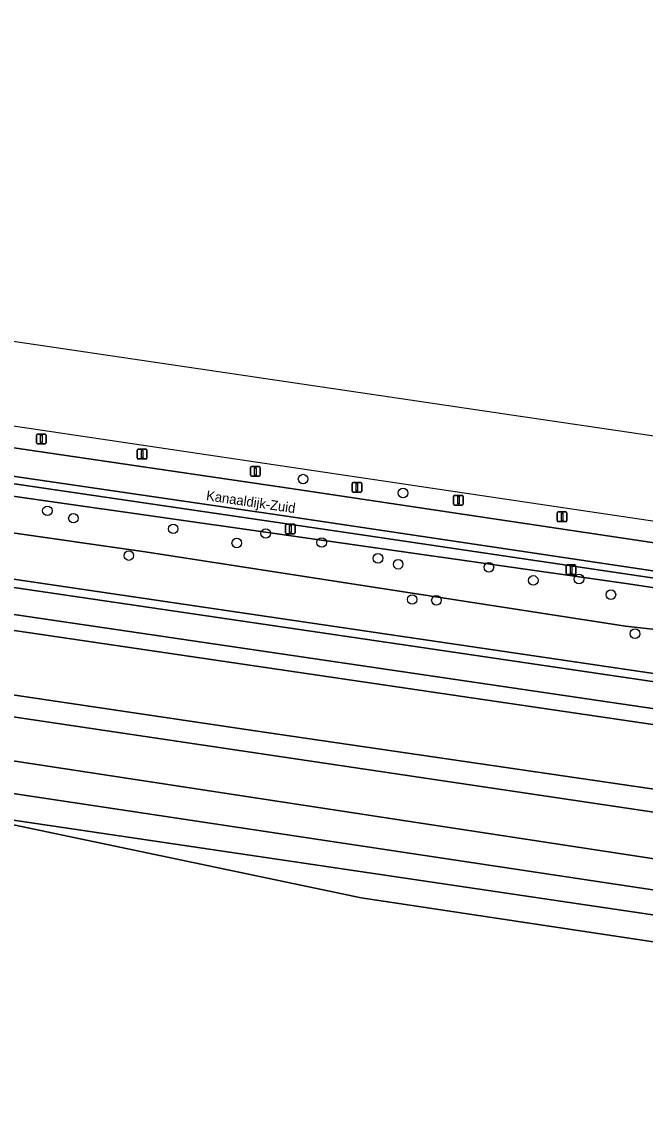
# Model space of a CAD drawing. Extents: x 163043 to 165076, y 382019 to 382874.
# Drawn here: x 163631.7 to 163695.7, y 382706.9 to 382817.6 of the extents above; entities that cross this region are included whole.
import ezdxf

# ---------------------------------------------------------------- set-up
doc = ezdxf.new("R2010")
doc.units = 0
for name, color, linetype in [('IMGEO_Afsluitpaal', 7, 'Continuous'), ('IMGEO_Berm_groen', 7, 'Continuous'), ('IMGEO_Boom', 7, 'Continuous'), ('IMGEO_Erf', 7, 'Continuous'), ('IMGEO_Fietspad_gesloten', 7, 'Continuous'), ('IMGEO_Groenvoorziening', 7, 'Continuous'), ('IMGEO_Hek', 7, 'Continuous'), ('IMGEO_Lichtmast', 7, 'Continuous'), ('IMGEO_Oever', 7, 'Continuous'), ('IMGEO_Openbare_ruimte_label', 7, 'Continuous'), ('IMGEO_Rijbaan_lokaal_gesloten', 7, 'Continuous'), ('IMGEO_Rijbaan_lokaal_halfverhard', 7, 'Continuous'), ('IMGEO_Waterloop', 7, 'Continuous')]:
    doc.layers.add(name, color=color, linetype=linetype)

msp = doc.modelspace()

# ---------------------------------------------------------------- linework, layer by layer
at = {"layer": 'IMGEO_Afsluitpaal'}
for p, q in [((163633.25, 382774.48), (163633.25, 382775.28)), ((163633.25, 382775.28), (163633.25, 382774.48)), ((163633.35, 382775.38), (163634.14, 382775.38)), ((163634.14, 382775.38), (163633.35, 382775.38)), ((163634.24, 382775.28), (163634.24, 382774.48)), ((163634.24, 382774.48), (163634.24, 382775.28)), ((163634.14, 382774.38), (163633.35, 382774.38)), ((163633.35, 382774.38), (163634.14, 382774.38)), ((163643.59, 382772.93), (163643.59, 382773.73)), ((163643.59, 382773.73), (163643.59, 382772.93)), ((163643.69, 382773.83), (163644.48, 382773.83)), ((163644.48, 382773.83), (163643.69, 382773.83)), ((163644.48, 382772.83), (163643.69, 382772.83)), ((163643.69, 382772.83), (163644.48, 382772.83)), ((163644.58, 382773.73), (163644.58, 382772.93)), ((163644.58, 382772.93), (163644.58, 382773.73)), ((163655.19, 382771.16), (163655.19, 382771.96)), ((163655.19, 382771.96), (163655.19, 382771.16)), ((163655.29, 382772.06), (163656.07, 382772.06)), ((163656.07, 382772.06), (163655.29, 382772.06)), ((163656.17, 382771.96), (163656.17, 382771.16)), ((163656.17, 382771.16), (163656.17, 382771.96)), ((163656.07, 382771.06), (163655.29, 382771.06)), ((163655.29, 382771.06), (163656.07, 382771.06)), ((163665.6, 382769.53), (163665.6, 382770.33)), ((163665.6, 382770.33), (163665.6, 382769.53)), ((163665.7, 382770.43), (163666.49, 382770.43)), ((163666.49, 382770.43), (163665.7, 382770.43)), ((163666.59, 382770.33), (163666.59, 382769.53)), ((163666.59, 382769.53), (163666.59, 382770.33)), ((163666.49, 382769.43), (163665.7, 382769.43)), ((163665.7, 382769.43), (163666.49, 382769.43)), ((163676.01, 382768.2), (163676.01, 382769)), ((163676.01, 382769), (163676.01, 382768.2)), ((163676.11, 382769.1), (163676.9, 382769.1)), ((163676.9, 382769.1), (163676.11, 382769.1)), ((163677, 382769), (163677, 382768.2)), ((163677, 382768.2), (163677, 382769)), ((163676.9, 382768.1), (163676.11, 382768.1)), ((163676.11, 382768.1), (163676.9, 382768.1)), ((163686.64, 382766.51), (163686.64, 382767.31)), ((163686.64, 382767.31), (163686.64, 382766.51)), ((163686.74, 382767.41), (163687.53, 382767.41)), ((163687.53, 382767.41), (163686.74, 382767.41)), ((163687.63, 382767.31), (163687.63, 382766.51)), ((163687.63, 382766.51), (163687.63, 382767.31)), ((163687.53, 382766.41), (163686.74, 382766.41)), ((163686.74, 382766.41), (163687.53, 382766.41))]:
    msp.add_line(p, q, dxfattribs=at)
for points in [[(163633.67, 382775.26), (163633.82, 382775.26), (163633.82, 382774.51), (163633.67, 382774.51), (163633.67, 382775.26)], [(163644.01, 382773.71), (163644.16, 382773.71), (163644.16, 382772.96), (163644.01, 382772.96), (163644.01, 382773.71)], [(163655.6, 382771.93), (163655.76, 382771.93), (163655.76, 382771.18), (163655.6, 382771.18), (163655.6, 382771.93)], [(163666.02, 382770.31), (163666.17, 382770.31), (163666.17, 382769.56), (163666.02, 382769.56), (163666.02, 382770.31)], [(163676.43, 382768.98), (163676.58, 382768.98), (163676.58, 382768.23), (163676.43, 382768.23), (163676.43, 382768.98)], [(163687.06, 382767.28), (163687.21, 382767.28), (163687.21, 382766.53), (163687.06, 382766.53), (163687.06, 382767.28)]]:
    msp.add_lwpolyline(points, dxfattribs=at)
for centre, start, end in [((163633.35, 382775.28), 90, 180), ((163633.35, 382775.28), 90, 180), ((163634.14, 382775.28), 0, 90), ((163634.14, 382775.28), 360, 90), ((163633.35, 382774.48), 180, 270), ((163633.35, 382774.48), 180, 270), ((163634.14, 382774.48), 270, 0), ((163634.14, 382774.48), 270, 0), ((163643.69, 382773.73), 90, 180), ((163643.69, 382773.73), 90, 180), ((163643.69, 382772.93), 180, 270), ((163643.69, 382772.93), 180, 270), ((163644.48, 382773.73), 0, 90), ((163644.48, 382773.73), 360, 90), ((163644.48, 382772.93), 270, 0), ((163644.48, 382772.93), 270, 0), ((163655.29, 382771.96), 90, 180), ((163655.29, 382771.96), 90, 180), ((163656.07, 382771.96), 0, 90), ((163656.07, 382771.96), 360, 90), ((163655.29, 382771.16), 180, 270), ((163655.29, 382771.16), 180, 270), ((163656.07, 382771.16), 270, 0), ((163656.07, 382771.16), 270, 0), ((163665.7, 382770.33), 90, 180), ((163665.7, 382770.33), 90, 180), ((163665.7, 382769.53), 180, 270), ((163665.7, 382769.53), 180, 270), ((163666.49, 382770.33), 0, 90), ((163666.49, 382770.33), 360, 90), ((163666.49, 382769.53), 270, 0), ((163666.49, 382769.53), 270, 0), ((163676.11, 382769), 90, 180), ((163676.11, 382769), 90, 180), ((163676.9, 382769), 0, 90), ((163676.9, 382769), 360, 90), ((163676.11, 382768.2), 180, 270), ((163676.11, 382768.2), 180, 270), ((163676.9, 382768.2), 270, 0), ((163676.9, 382768.2), 270, 0), ((163686.74, 382767.31), 90, 180), ((163686.74, 382767.31), 90, 180), ((163687.53, 382767.31), 0, 90), ((163687.53, 382767.31), 360, 90), ((163686.74, 382766.51), 180, 270), ((163686.74, 382766.51), 180, 270), ((163687.53, 382766.51), 270, 0), ((163687.53, 382766.51), 270, 0)]:
    msp.add_arc(centre, 0.1, start, end, dxfattribs=at)
at = {"layer": 'IMGEO_Berm_groen'}
msp.add_lwpolyline([(163557.09, 382767.74), (163556.9, 382766.15), (163666.72, 382750), (163831.84, 382725.71), (163843.6, 382723.98), (163843.81, 382725.57)], close=True, dxfattribs=at)
at = {"layer": 'IMGEO_Boom'}
for centre in [(163660.58, 382770.77), (163670.83, 382769.34), (163634.37, 382767.52), (163637.04, 382766.76), (163647.27, 382765.67), (163656.75, 382765.2), (163653.78, 382764.22), (163662.49, 382764.27), (163642.72, 382762.93), (163668.26, 382762.65), (163670.33, 382762.04), (163679.63, 382761.73), (163684.18, 382760.39), (163688.87, 382760.53), (163671.77, 382758.43), (163674.25, 382758.35), (163692.14, 382758.93), (163694.61, 382754.93)]:
    msp.add_circle(centre, 0.489, dxfattribs=at)
at = {"layer": 'IMGEO_Erf'}
for points in [[(163755.9, 382730.2), (163716.68, 382736.05), (163656.59, 382744.84), (163592.57, 382754.34), (163555.64, 382759.8), (163555.43, 382758.28), (163551.14, 382758.95), (163550.79, 382757.63)], [(163550, 382756.08), (163551.21, 382757), (163551.71, 382756.34), (163551.82, 382757.15), (163552.77, 382757.02), (163552.78, 382757.12), (163555.08, 382756.83), (163555.19, 382757.61), (163606.71, 382750), (163755.55, 382727.85)], [(163753.68, 382717.65), (163616.32, 382737.96)], [(163517.69, 382649.12), (163518.33, 382648.93), (163518.9, 382648.81), (163519.65, 382648.65), (163520.31, 382648.5), (163520.96, 382648.34), (163520.6, 382646.87), (163561.84, 382636.86), (163562.82, 382641.11), (163587.18, 382635.48), (163586.11, 382630.84), (163589.84, 382629.98), (163598.25, 382663.73), (163605.6, 382662.09), (163616.25, 382704.79), (163625.48, 382736.46), (163666.55, 382727.85), (163754.11, 382714.7), (163754.37, 382714.66)], [(163838.28, 382702.34), (163806.26, 382707.16), (163779.91, 382710.83), (163754.37, 382714.66), (163754.11, 382714.7), (163666.55, 382727.85), (163625.48, 382736.46), (163616.25, 382704.79), (163605.6, 382662.09), (163598.25, 382663.73), (163589.84, 382629.98), (163595.26, 382628.83), (163593.77, 382621.82), (163604.54, 382619.29), (163600.21, 382601.52), (163589.43, 382604.17), (163587.96, 382597.8), (163587.58, 382596.07), (163601.96, 382592.39), (163617.25, 382589.09), (163628.73, 382587.46), (163644.41, 382585.22), (163644.12, 382583.22), (163654.99, 382581.68)]]:
    msp.add_lwpolyline(points, dxfattribs=at)
at = {"layer": 'IMGEO_Fietspad_gesloten'}
for points in [[(163481.33, 382792.88), (163658.89, 382766.97), (163694.37, 382761.68), (163717.86, 382758.17), (163777.02, 382749.58), (163865.22, 382736.76), (163935.2, 382726.45), (163935.71, 382729.35), (163894.24, 382735.48), (163777.46, 382752.55), (163718.28, 382761.09), (163718.27, 382760.99), (163694.75, 382764.5), (163659.31, 382769.79), (163600.16, 382778.49), (163481.75, 382795.75)], [(164027.35, 382701.08), (164001.81, 382704.9), (163972.99, 382709.21), (163941.3, 382713.95), (163899.36, 382720.17), (163864.59, 382725.29), (163853.75, 382726.93), (163828.34, 382730.66), (163782.57, 382737.3), (163742.98, 382743.16), (163672.74, 382753.5), (163608.81, 382762.9), (163587.4, 382766.11), (163537.53, 382773.31), (163534.17, 382773.83)], [(163534.96, 382771), (163538.05, 382770.54), (163546.52, 382769.3), (163549.89, 382768.8), (163553.48, 382768.27), (163557.09, 382767.74), (163843.81, 382725.57), (163846.96, 382725.11)]]:
    msp.add_lwpolyline(points, dxfattribs=at)
at = {"layer": 'IMGEO_Groenvoorziening'}
for points in [[(163901.57, 382725.6), (163891.58, 382726.84), (163814.14, 382738.31), (163792.78, 382741.61), (163745.19, 382750), (163693.63, 382755.7), (163644.4, 382763.31), (163599.03, 382769.82), (163550.48, 382777.74), (163531.31, 382780.73), (163500, 382785.31), (163403.56, 382799.39), (163402.77, 382799.54), (163335.61, 382812.21), (163322.88, 382814.5)], [(163481.75, 382795.75), (163600.16, 382778.49), (163659.31, 382769.79), (163694.75, 382764.5), (163718.27, 382760.99), (163718.28, 382761.09), (163777.46, 382752.55), (163894.24, 382735.48), (163935.71, 382729.35), (163983.8, 382722.23), (164052.71, 382712.03), (164052.69, 382711.93), (164086.54, 382706.99), (164187.43, 382691.72), (164210.53, 382688.01), (164226.5, 382685.65), (164235.35, 382684.54), (164278.14, 382678.22), (164284.35, 382677.28), (164396.3, 382660.19)], [(163893.44, 382737.78), (163842.64, 382744.9), (163808.82, 382750), (163787.83, 382753.17), (163750, 382758.53), (163695.04, 382766.67), (163550.36, 382788.13), (163500, 382795.74)], [(163942.52, 382724.63), (163797.09, 382745.94), (163724.04, 382756.55), (163665.19, 382765.27), (163586.49, 382776.8), (163535.08, 382784.39), (163477.86, 382792.74)], [(163500, 382787.56), (163548.66, 382779.98), (163558.31, 382778.65), (163599.59, 382773.47), (163692, 382760.32), (163694.14, 382759.99), (163759.96, 382750), (163780.57, 382747.06), (163793.38, 382745.36), (163843.66, 382737.95), (163892.47, 382731.14), (163941.47, 382723.93)], [(164518.36, 382627.93), (164282.56, 382663.33), (164217.65, 382673.07), (164197.42, 382676.27), (164103.91, 382690.52), (164080.42, 382694.02), (163981.6, 382708.67), (163943.51, 382714.37), (163916.5, 382718.52), (163873.33, 382724.84), (163846.1, 382728.88), (163828.8, 382731.36), (163693.06, 382751.36), (163550.62, 382772.33), (163535.41, 382774.6), (163500, 382779.47)], [(163500, 382779.47), (163535.41, 382774.6), (163550.62, 382772.33), (163693.06, 382751.36), (163828.8, 382731.36), (163846.1, 382728.88), (163873.33, 382724.84), (163916.5, 382718.52), (163943.51, 382714.37), (163981.6, 382708.67), (164080.42, 382694.02), (164103.91, 382690.52), (164197.42, 382676.27), (164217.65, 382673.07), (164282.56, 382663.33), (164518.36, 382627.93)], [(163534.17, 382773.83), (163537.53, 382773.31), (163587.4, 382766.11), (163608.81, 382762.9), (163672.74, 382753.5), (163742.98, 382743.16), (163782.57, 382737.3), (163828.34, 382730.66), (163853.75, 382726.93), (163864.59, 382725.29), (163899.36, 382720.17), (163941.3, 382713.95)]]:
    msp.add_lwpolyline(points, dxfattribs=at)
at = {"layer": 'IMGEO_Hek'}
for points in [[(163693.06, 382751.36), (163550.62, 382772.33), (163535.41, 382774.6)], [(163981.6, 382708.67), (163943.51, 382714.37), (163916.5, 382718.52), (163873.33, 382724.84), (163846.1, 382728.88), (163828.8, 382731.36), (163693.06, 382751.36)]]:
    msp.add_lwpolyline(points, dxfattribs=at)
at = {"layer": 'IMGEO_Lichtmast'}
for p, q in [((163658.88, 382766.15), (163659.67, 382766.15)), ((163659.67, 382766.15), (163658.88, 382766.15)), ((163658.78, 382765.25), (163658.78, 382766.05)), ((163658.78, 382766.05), (163658.78, 382765.25)), ((163659.67, 382765.15), (163658.88, 382765.15)), ((163658.88, 382765.15), (163659.67, 382765.15)), ((163659.77, 382766.05), (163659.77, 382765.25)), ((163659.77, 382765.25), (163659.77, 382766.05)), ((163687.56, 382761.09), (163687.56, 382761.89)), ((163687.56, 382761.89), (163687.56, 382761.09)), ((163687.66, 382761.99), (163688.45, 382761.99)), ((163688.45, 382761.99), (163687.66, 382761.99)), ((163688.55, 382761.89), (163688.55, 382761.09)), ((163688.55, 382761.09), (163688.55, 382761.89)), ((163688.45, 382760.99), (163687.66, 382760.99)), ((163687.66, 382760.99), (163688.45, 382760.99))]:
    msp.add_line(p, q, dxfattribs=at)
for points in [[(163659.2, 382766.03), (163659.35, 382766.03), (163659.35, 382765.28), (163659.2, 382765.28), (163659.2, 382766.03)], [(163687.98, 382761.86), (163688.13, 382761.86), (163688.13, 382761.11), (163687.98, 382761.11), (163687.98, 382761.86)]]:
    msp.add_lwpolyline(points, dxfattribs=at)
for centre, start, end in [((163658.88, 382766.05), 90, 180), ((163658.88, 382766.05), 90, 180), ((163659.67, 382766.05), 0, 90), ((163659.67, 382766.05), 360, 90), ((163658.88, 382765.25), 180, 270), ((163658.88, 382765.25), 180, 270), ((163659.67, 382765.25), 270, 0), ((163659.67, 382765.25), 270, 0), ((163687.66, 382761.89), 90, 180), ((163687.66, 382761.89), 90, 180), ((163688.45, 382761.89), 0, 90), ((163688.45, 382761.89), 360, 90), ((163687.66, 382761.09), 180, 270), ((163687.66, 382761.09), 180, 270), ((163688.45, 382761.09), 270, 0), ((163688.45, 382761.09), 270, 0)]:
    msp.add_arc(centre, 0.1, start, end, dxfattribs=at)
at = {"layer": 'IMGEO_Oever'}
for points in [[(163755.55, 382727.85), (163606.71, 382750), (163555.19, 382757.61)], [(163550.24, 382753.72), (163551.31, 382753.63), (163551.87, 382753.58), (163554.57, 382753.35), (163556.34, 382753.2), (163562.84, 382752.3), (163751.82, 382723.43), (163752.98, 382722.72), (163752.82, 382720.79), (163752.03, 382720.32), (163612.9, 382741.27), (163607.89, 382736.86), (163595.91, 382738.22), (163590.56, 382745.01), (163555.74, 382750.53)], [(163548.67, 382746.2), (163549.28, 382746.1), (163549.54, 382747.78), (163550.49, 382747.64), (163550.42, 382747.13), (163550.97, 382747.04), (163551.32, 382746.99), (163553.16, 382746.69), (163553.28, 382747.47), (163553.67, 382747.12), (163589.61, 382741.91), (163594.68, 382735.09), (163609.51, 382732.91), (163616.32, 382737.96), (163753.68, 382717.65)]]:
    msp.add_lwpolyline(points, dxfattribs=at)
at = {"layer": 'IMGEO_Rijbaan_lokaal_gesloten'}
for points in [[(164000, 382700.98), (163854.78, 382722.34), (163850.49, 382722.97), (163847.72, 382723.38), (163843.6, 382723.98), (163831.84, 382725.71), (163666.72, 382750), (163556.9, 382766.15), (163552.59, 382766.79), (163550.54, 382767.09), (163546.3, 382767.71), (163537.82, 382768.96), (163533.74, 382769.56), (163530.74, 382770), (163526.73, 382770.59), (163500, 382774.52)], [(163552.85, 382760.22), (163555.64, 382759.8), (163592.57, 382754.34), (163656.59, 382744.84), (163716.68, 382736.05), (163755.9, 382730.2)]]:
    msp.add_lwpolyline(points, dxfattribs=at)
at = {"layer": 'IMGEO_Rijbaan_lokaal_halfverhard'}
for points in [[(163477.86, 382792.74), (163535.08, 382784.39), (163586.49, 382776.8), (163665.19, 382765.27), (163724.04, 382756.55), (163797.09, 382745.94), (163942.52, 382724.63), (163982.95, 382718.82), (164038.68, 382710.5), (164106.21, 382700.45), (164167.93, 382691.09), (164227.93, 382681.9), (164243.96, 382679.59), (164325.74, 382667.17), (164396.2, 382656.23)], [(163777.02, 382749.58), (163717.86, 382758.17), (163694.37, 382761.68), (163658.89, 382766.97), (163481.33, 382792.88)]]:
    msp.add_lwpolyline(points, dxfattribs=at)
at = {"layer": 'IMGEO_Waterloop'}
for points in [[(163123.71, 382866.34), (163125.44, 382874.2), (163542.42, 382797.92), (163683.11, 382777.18), (164147.9, 382708.69), (165075.56, 382573.63)], [(163961.29, 382721.23), (163941.47, 382723.93), (163892.47, 382731.14), (163843.66, 382737.95), (163793.38, 382745.36), (163780.57, 382747.06), (163759.96, 382750), (163694.14, 382759.99), (163692, 382760.32), (163599.59, 382773.47), (163558.31, 382778.65), (163548.66, 382779.98), (163500, 382787.56), (163422.96, 382799.57), (163403.34, 382803.03), (163359.3, 382810.82), (163337.61, 382814.84), (163323.3, 382816.84)], [(163322.88, 382814.5), (163335.61, 382812.21), (163402.77, 382799.54), (163403.56, 382799.39), (163500, 382785.31), (163531.31, 382780.73), (163550.48, 382777.74), (163599.03, 382769.82), (163644.4, 382763.31), (163693.63, 382755.7), (163745.19, 382750), (163792.78, 382741.61), (163814.14, 382738.31), (163891.58, 382726.84), (163901.57, 382725.6), (163960.72, 382718.96)], [(164390.46, 382663.82), (164301.17, 382677.11), (164284.68, 382679.59), (164000, 382722.46), (163984.26, 382724.67), (163957.08, 382728.48), (163893.44, 382737.78), (163842.64, 382744.9), (163808.82, 382750), (163787.83, 382753.17), (163750, 382758.53), (163695.04, 382766.67), (163550.36, 382788.13), (163500, 382795.74)], [(163550.08, 382751.43), (163550.93, 382751.29), (163551.54, 382751.2), (163554.2, 382750.77), (163555.74, 382750.53), (163590.56, 382745.01), (163595.91, 382738.22), (163607.89, 382736.86), (163612.9, 382741.27), (163752.03, 382720.32), (163752.82, 382720.79), (163752.98, 382722.72), (163751.82, 382723.43), (163562.84, 382752.3)]]:
    msp.add_lwpolyline(points, dxfattribs=at)

# ---------------------------------------------------------------- texts
at = {"layer": 'IMGEO_Openbare_ruimte_label'}
msp.add_text('Kanaaldijk-Zuid', height=1, rotation=351.6591, dxfattribs=at).set_placement((163650.6, 382768.61))

doc.saveas('drawing.dxf')
